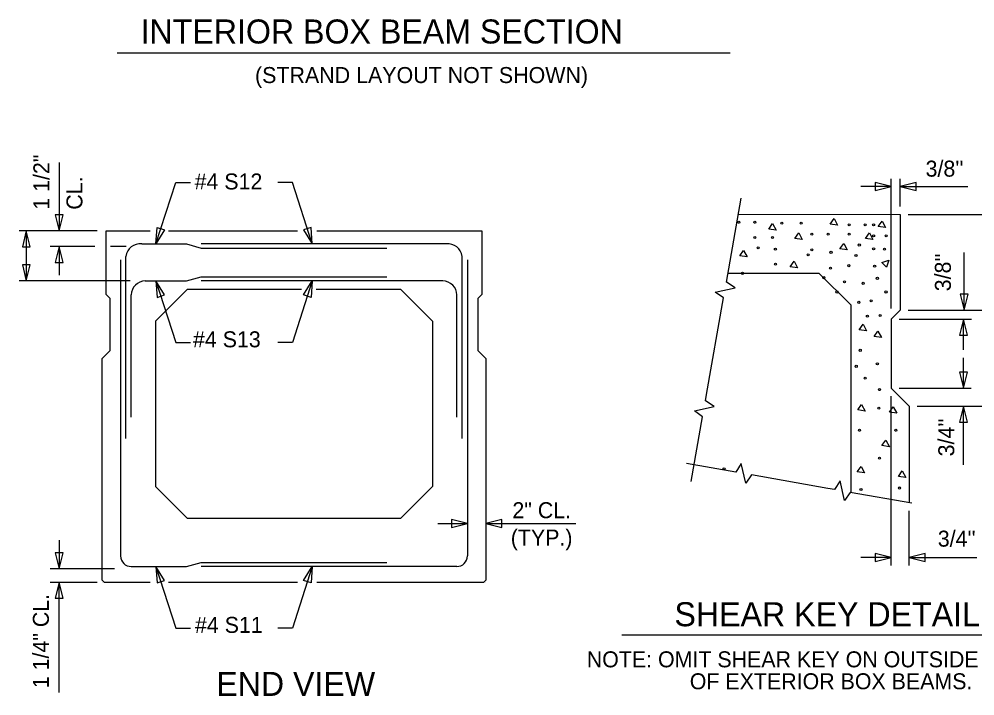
# Model space of a CAD drawing. Extents: x -38 to 94, y -165 to 80.
# Drawn here: x -26.05 to -18.57, y -154.39 to -149.1 of the extents above; entities that cross this region are included whole.
import ezdxf

# ---------------------------------------------------------------- set-up
doc = ezdxf.new("R2010")
doc.units = 0
for name, color, linetype in [('Arrowhead Terminators', 7, 'Continuous'), ('Arrowhead Terminators CELL', 7, 'Continuous'), ('Box Beam', 7, 'Continuous'), ('Dimension Lines', 7, 'Continuous'), ('Rebar Lines', 7, 'Continuous'), ('Sub End Bent Cap Lines CELL', 7, 'Continuous'), ('Subtitle Text', 7, 'Continuous'), ('Text', 7, 'Continuous'), ('User Information Notes', 7, 'Continuous')]:
    doc.layers.add(name, color=color, linetype=linetype)

# ---------------------------------------------------------------- blocks, each defined once
blk = doc.blocks.new('AH')
at = {"layer": 'Sub End Bent Cap Lines CELL'}
blk.add_lwpolyline([(0, 0), (-1.25, 0.312), (-1.25, -0.312)], close=True, dxfattribs=at)

msp = doc.modelspace()

# ---------------------------------------------------------------- linework, layer by layer
at = {"layer": 'Arrowhead Terminators'}
for points in [[(-19.2269, -150.4043), (-19.3519, -150.3731), (-19.3519, -150.4356)], [(-19.1564, -150.4043), (-19.0314, -150.4356), (-19.0314, -150.3731)], [(-18.6572, -151.3733), (-18.6259, -151.2483), (-18.6884, -151.2483)], [(-18.6607, -151.4438), (-18.6919, -151.5688), (-18.6294, -151.5688)], [(-18.6607, -151.9826), (-18.6294, -151.8576), (-18.6919, -151.8576)], [(-18.6607, -152.1232), (-18.6919, -152.2482), (-18.6294, -152.2482)]]:
    msp.add_lwpolyline(points, close=True, dxfattribs=at)
at = {"layer": 'Arrowhead Terminators CELL'}
for points in [[(-25.7339, -150.7508), (-25.7026, -150.6258), (-25.7651, -150.6258)], [(-24.9768, -150.8547), (-24.9684, -150.7261), (-24.9089, -150.7452)], [(-23.7541, -150.8547), (-23.7625, -150.7261), (-23.822, -150.7452)], [(-25.7339, -150.8739), (-25.7651, -150.9989), (-25.7026, -150.9989)], [(-24.9768, -151.144), (-24.9684, -151.2726), (-24.9089, -151.2535)], [(-23.7541, -151.144), (-23.7625, -151.2726), (-23.822, -151.2535)], [(-22.5399, -153.0418), (-22.6649, -153.0105), (-22.6649, -153.073)], [(-22.3968, -153.0418), (-22.2718, -153.073), (-22.2718, -153.0105)], [(-25.7339, -153.3953), (-25.7026, -153.2703), (-25.7651, -153.2703)], [(-19.2267, -153.3053), (-19.3517, -153.2741), (-19.3517, -153.3366)], [(-19.086, -153.3053), (-18.961, -153.3366), (-18.961, -153.2741)], [(-24.9768, -153.3772), (-24.9684, -153.5057), (-24.9089, -153.4867)], [(-23.7541, -153.3772), (-23.7625, -153.5057), (-23.822, -153.4867)], [(-25.7339, -153.5008), (-25.7651, -153.6258), (-25.7026, -153.6258)]]:
    msp.add_lwpolyline(points, close=True, dxfattribs=at)
at = {"layer": 'Box Beam'}
for p, q in [((-25.3659, -151.2508), (-25.3659, -150.7508)), ((-25.3659, -150.7508), (-25.0209, -150.7508)), ((-24.8792, -150.7508), (-23.8687, -150.7508)), ((-23.7179, -150.7508), (-22.4281, -150.7508)), ((-22.4281, -150.7508), (-22.4281, -151.2508)), ((-20.5034, -151.0817), (-19.7919, -151.0817)), ((-19.7919, -151.0817), (-19.5419, -151.3318)), ((-25.3346, -151.2821), (-25.3659, -151.2508)), ((-25.3346, -151.6884), (-25.3346, -151.2821)), ((-24.9804, -151.4592), (-24.7304, -151.2091)), ((-24.7304, -151.2091), (-23.8378, -151.2091)), ((-23.7238, -151.2091), (-23.0636, -151.2091)), ((-23.0636, -151.2091), (-22.8136, -151.4592)), ((-22.4281, -151.2508), (-22.4593, -151.2821)), ((-22.4589, -151.2816), (-22.4589, -151.6879)), ((-19.5419, -151.3318), (-19.5419, -152.798)), ((-24.9804, -151.4592), (-24.9804, -152.7507)), ((-22.8136, -151.4592), (-22.8136, -152.7507)), ((-25.3972, -151.7509), (-25.3346, -151.6884)), ((-22.4593, -151.6884), (-22.3968, -151.7509)), ((-25.3972, -153.4829), (-25.3972, -151.7509)), ((-22.3968, -151.7509), (-22.3968, -153.4829)), ((-24.7304, -153.0007), (-24.9804, -152.7507)), ((-22.8136, -152.7507), (-23.0636, -153.0007)), ((-23.0636, -153.0007), (-24.7304, -153.0007)), ((-25.3972, -153.4829), (-25.3793, -153.5008)), ((-25.0209, -153.5008), (-25.3793, -153.5008)), ((-23.8687, -153.5008), (-24.8792, -153.5008)), ((-22.4147, -153.5008), (-23.7179, -153.5008)), ((-22.3968, -153.4829), (-22.4147, -153.5008))]:
    msp.add_line(p, q, dxfattribs=at)
for points in [[(-20.6706, -152.0306), (-20.5379, -151.2771), (-20.6027, -151.2326), (-20.4477, -151.1976), (-20.5162, -151.154), (-20.3994, -150.4955)], [(-20.4216, -150.6206), (-19.1564, -150.6233), (-19.1564, -151.3733), (-19.2269, -151.4438), (-19.2267, -151.9826), (-19.086, -152.1232), (-19.086, -152.8782)], [(-19.7035, -150.6988), (-19.6736, -150.6562), (-19.646, -150.7072), (-19.7035, -150.6988)], [(-19.3281, -150.7185), (-19.2983, -150.676), (-19.2707, -150.727), (-19.3281, -150.7185)], [(-20.1843, -150.7383), (-20.1544, -150.6958), (-20.1268, -150.7468), (-20.1843, -150.7383)], [(-19.9801, -150.8108), (-19.9503, -150.7682), (-19.9227, -150.8192), (-19.9801, -150.8108)], [(-19.4269, -150.8108), (-19.397, -150.7682), (-19.3694, -150.8192), (-19.4269, -150.8108)], [(-20.4114, -150.947), (-20.3815, -150.9045), (-20.3539, -150.9555), (-20.4114, -150.947)], [(-19.6284, -150.8928), (-19.5985, -150.8502), (-19.5709, -150.9012), (-19.6284, -150.8928)], [(-19.2646, -151.0369), (-19.3014, -151.0002), (-19.2464, -150.9819), (-19.2646, -151.0369)], [(-20.016, -151.0323), (-19.9861, -150.9898), (-19.9585, -151.0408), (-20.016, -151.0323)], [(-19.4773, -151.5253), (-19.4474, -151.4827), (-19.4198, -151.5337), (-19.4773, -151.5253)], [(-19.3609, -151.5789), (-19.331, -151.5363), (-19.3034, -151.5873), (-19.3609, -151.5789)], [(-20.7909, -152.7128), (-20.7015, -152.2054), (-20.7663, -152.1608), (-20.6113, -152.1258), (-20.6798, -152.0822), (-20.6707, -152.0306)], [(-19.4888, -152.1526), (-19.459, -152.11), (-19.4314, -152.161), (-19.4888, -152.1526)], [(-19.2409, -152.1705), (-19.211, -152.1279), (-19.1835, -152.1789), (-19.2409, -152.1705)], [(-19.2989, -152.4317), (-19.2691, -152.3891), (-19.2415, -152.4401), (-19.2989, -152.4317)], [(-19.722, -152.7664), (-20.32, -152.661), (-20.3646, -152.7258), (-20.3996, -152.5708), (-20.4432, -152.6393), (-20.8273, -152.5712)], [(-19.4922, -152.6368), (-19.4623, -152.5943), (-19.4347, -152.6453), (-19.4922, -152.6368)], [(-19.171, -152.672), (-19.1411, -152.6294), (-19.1135, -152.6804), (-19.171, -152.672)], [(-19.066, -152.8818), (-19.5471, -152.797), (-19.5917, -152.8618), (-19.6267, -152.7068), (-19.6703, -152.7754), (-19.7219, -152.7662)]]:
    msp.add_lwpolyline(points, dxfattribs=at)
for centre in [(-20.4183, -150.685), (-20.2931, -150.685), (-20.0824, -150.6916), (-19.9309, -150.6916), (-19.5555, -150.7048), (-19.4304, -150.7048), (-19.3645, -150.7048), (-20.2931, -150.8037), (-20.1549, -150.8037), (-19.8481, -150.7773), (-19.7202, -150.7773), (-19.5555, -150.7773), (-19.3645, -150.7905), (-19.2657, -150.7905), (-20.2675, -150.885), (-20.1326, -150.8947), (-19.8481, -150.9004), (-19.4765, -150.863), (-19.3643, -150.8928), (-19.2793, -150.8947), (-19.876, -150.9393), (-19.6977, -150.9199), (-19.5024, -150.945), (-20.1318, -151.0129), (-19.7016, -151.044), (-19.5581, -151.0245), (-19.3566, -151.0284), (-20.3892, -151.0843), (-19.7533, -151.1179), (-19.3351, -151.1235), (-19.5916, -151.1514), (-19.4466, -151.1625), (-19.6512, -151.23), (-19.2674, -151.23), (-19.4806, -151.3114), (-19.3837, -151.2997), (-19.4131, -151.419), (-19.3127, -151.4135), (-19.4689, -151.6868), (-19.5, -151.8114), (-19.3351, -151.7927), (-19.4302, -151.9045), (-19.3178, -151.9936), (-19.3238, -152.1386), (-19.4745, -152.3115), (-19.19, -152.3115), (-19.3183, -152.529), (-20.5341, -152.6126), (-19.4633, -152.7744), (-19.1621, -152.7633)]:
    msp.add_circle(centre, 0.0082, dxfattribs=at)
at = {"layer": 'Dimension Lines'}
for p, q in [((-25.7339, -150.2184), (-25.7339, -150.7508)), ((-19.2269, -151.3601), (-19.2269, -150.344)), ((-19.1564, -150.5608), (-19.1564, -150.344)), ((-19.2269, -150.4043), (-19.4649, -150.4043)), ((-19.1564, -150.4043), (-18.6287, -150.4043)), ((-19.0939, -150.6233), (-18.3216, -150.6233)), ((-25.4374, -150.7508), (-26.0469, -150.7508)), ((-25.9905, -150.7508), (-25.9905, -151.144)), ((-25.454, -150.8739), (-25.8054, -150.8739)), ((-25.7339, -150.8739), (-25.7339, -151.0974)), ((-25.2108, -150.8739), (-25.3317, -150.8739)), ((-18.6572, -151.3733), (-18.6572, -150.9221)), ((-25.1777, -151.144), (-26.0469, -151.144)), ((-19.0939, -151.3733), (-18.3216, -151.3733)), ((-19.1644, -151.4438), (-18.5982, -151.4438)), ((-18.6607, -151.6818), (-18.6607, -151.4438)), ((-18.6607, -151.9826), (-18.6607, -151.7446)), ((-19.1642, -151.9826), (-18.6017, -151.9826)), ((-19.2267, -153.3678), (-19.2267, -152.0451)), ((-19.0235, -152.1232), (-18.3216, -152.1232)), ((-18.6607, -152.5819), (-18.6607, -152.1232)), ((-19.086, -153.3678), (-19.086, -152.9407)), ((-22.7723, -153.0418), (-22.5399, -153.0418)), ((-22.3968, -153.0418), (-21.6938, -153.0418)), ((-25.7339, -153.1719), (-25.7339, -153.3953)), ((-19.2267, -153.3053), (-19.4647, -153.3053)), ((-19.086, -153.3053), (-18.5584, -153.3053)), ((-25.3021, -153.3953), (-25.8054, -153.3953)), ((-25.4374, -153.5008), (-25.8054, -153.5008)), ((-25.7339, -154.3624), (-25.7339, -153.5008))]:
    msp.add_line(p, q, dxfattribs=at)
for points in [[(-24.9768, -150.8547), (-24.8224, -150.3729), (-24.7065, -150.3729)], [(-23.7541, -150.8547), (-23.9085, -150.3729), (-24.0244, -150.3729)], [(-24.9768, -151.144), (-24.8224, -151.6258), (-24.7065, -151.6258)], [(-23.7541, -151.144), (-23.9085, -151.6258), (-24.0244, -151.6258)], [(-24.9768, -153.3772), (-24.8224, -153.859), (-24.7065, -153.859)], [(-23.7541, -153.3772), (-23.9085, -153.859), (-24.0244, -153.859)]]:
    msp.add_lwpolyline(points, dxfattribs=at)
at = {"layer": 'Rebar Lines'}
for p, q in [((-25.0874, -150.8547), (-24.7367, -150.8547)), ((-24.7367, -150.8547), (-24.6221, -150.8873)), ((-22.707, -150.8547), (-24.6221, -150.8547)), ((-24.6221, -150.8873), (-23.1722, -150.8873)), ((-25.2533, -150.9799), (-25.2533, -153.2937)), ((-25.2116, -152.3758), (-25.2116, -150.9515)), ((-22.5827, -152.3758), (-22.5827, -150.9515)), ((-22.541, -150.9799), (-22.541, -153.2937)), ((-24.7367, -151.144), (-24.6221, -151.1114)), ((-24.6221, -151.1114), (-23.1722, -151.1114)), ((-25.0606, -151.144), (-24.7367, -151.144)), ((-22.7337, -151.144), (-24.6221, -151.144)), ((-25.17, -152.2091), (-25.17, -151.2534)), ((-22.6243, -152.2091), (-22.6243, -151.2534)), ((-24.7367, -153.3772), (-24.6221, -153.3446)), ((-24.6221, -153.3446), (-23.1722, -153.3446)), ((-25.1699, -153.3772), (-24.7367, -153.3772)), ((-22.6244, -153.3772), (-24.6221, -153.3772))]:
    msp.add_line(p, q, dxfattribs=at)
for centre, radius, start, end in [((-25.1011, -150.9652), 0.1114, 82.91815, 172.91815), ((-22.6932, -150.9652), 0.1114, 7.08185, 97.08185), ((-25.0606, -151.2534), 0.1094, 90, 180), ((-22.7337, -151.2534), 0.1094, 0, 90), ((-25.1699, -153.2937), 0.0834, 180, 270), ((-22.6244, -153.2937), 0.0834, 270, 0)]:
    msp.add_arc(centre, radius, start, end, dxfattribs=at)
at = {"layer": 'Subtitle Text'}
for p, q in [((-25.2793, -149.3589), (-20.4851, -149.3589)), ((-17.7549, -153.9149), (-21.3331, -153.9149))]:
    msp.add_line(p, q, dxfattribs=at)
at = {"layer": 'User Information Notes'}
for p, q in [((-25.3972, -153.5008), (-25.3972, -153.5008)), ((-22.3968, -153.5008), (-22.3968, -153.5008))]:
    msp.add_line(p, q, dxfattribs=at)

# ---------------------------------------------------------------- block references
at = {"layer": 'Arrowhead Terminators CELL', "xscale": 0.1, "yscale": 0.10000000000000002}
for p, rotation in [((-25.9905, -150.7508), 90), ((-25.9905, -151.144), -90)]:
    msp.add_blockref('AH', p, dxfattribs=dict(at, rotation=rotation))

# ---------------------------------------------------------------- texts
at = {"layer": 'Subtitle Text'}
for s, height, p in [('INTERIOR BOX BEAM SECTION', 0.188, (-25.0973, -149.287)), ('SHEAR KEY DETAIL', 0.188021, (-20.922, -153.8441)), ('END VIEW', 0.188, (-24.5055, -154.3887))]:
    msp.add_text(s, height=height, dxfattribs=at).set_placement(p)
at = {"layer": 'Text'}
for s, height, p in [('(STRAND LAYOUT NOT SHOWN)', 0.125206, (-24.2022, -149.5963)), ("3/8''", 0.125, (-18.958, -150.3282)), ('#4 S12', 0.125, (-24.6747, -150.4283)), ('#4 S13', 0.125, (-24.6872, -151.6628)), ('2" CL.', 0.125, (-22.1892, -152.9991)), ('(TYP.)', 0.125, (-22.2022, -153.2129)), ("3/4''", 0.125, (-18.8626, -153.2217)), ('#4 S11', 0.125, (-24.6715, -153.8959)), ('NOTE: OMIT SHEAR KEY ON OUTSIDE FACE', 0.125, (-21.6078, -154.1653)), ('OF EXTERIOR BOX BEAMS.', 0.125, (-20.8022, -154.337))]:
    msp.add_text(s, height=height, dxfattribs=at).set_placement(p)
for s, p in [('1 1/2"', (-25.8105, -150.5867)), ('CL.', (-25.5518, -150.5867)), ("3/8''", (-18.7602, -151.2247)), ("3/4''", (-18.7338, -152.5157)), ('1 1/4" CL.', (-25.8145, -154.3287))]:
    msp.add_text(s, height=0.125, rotation=90, dxfattribs=at).set_placement(p)

doc.saveas('drawing.dxf')
